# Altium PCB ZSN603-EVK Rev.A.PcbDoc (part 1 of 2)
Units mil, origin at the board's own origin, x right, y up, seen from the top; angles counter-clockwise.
Board outline 3937.01 x 3149.67 mil, 2 copper layers (Top Layer, Bottom Layer); 139 components, 76 nets, 380 pads, 360 vias.
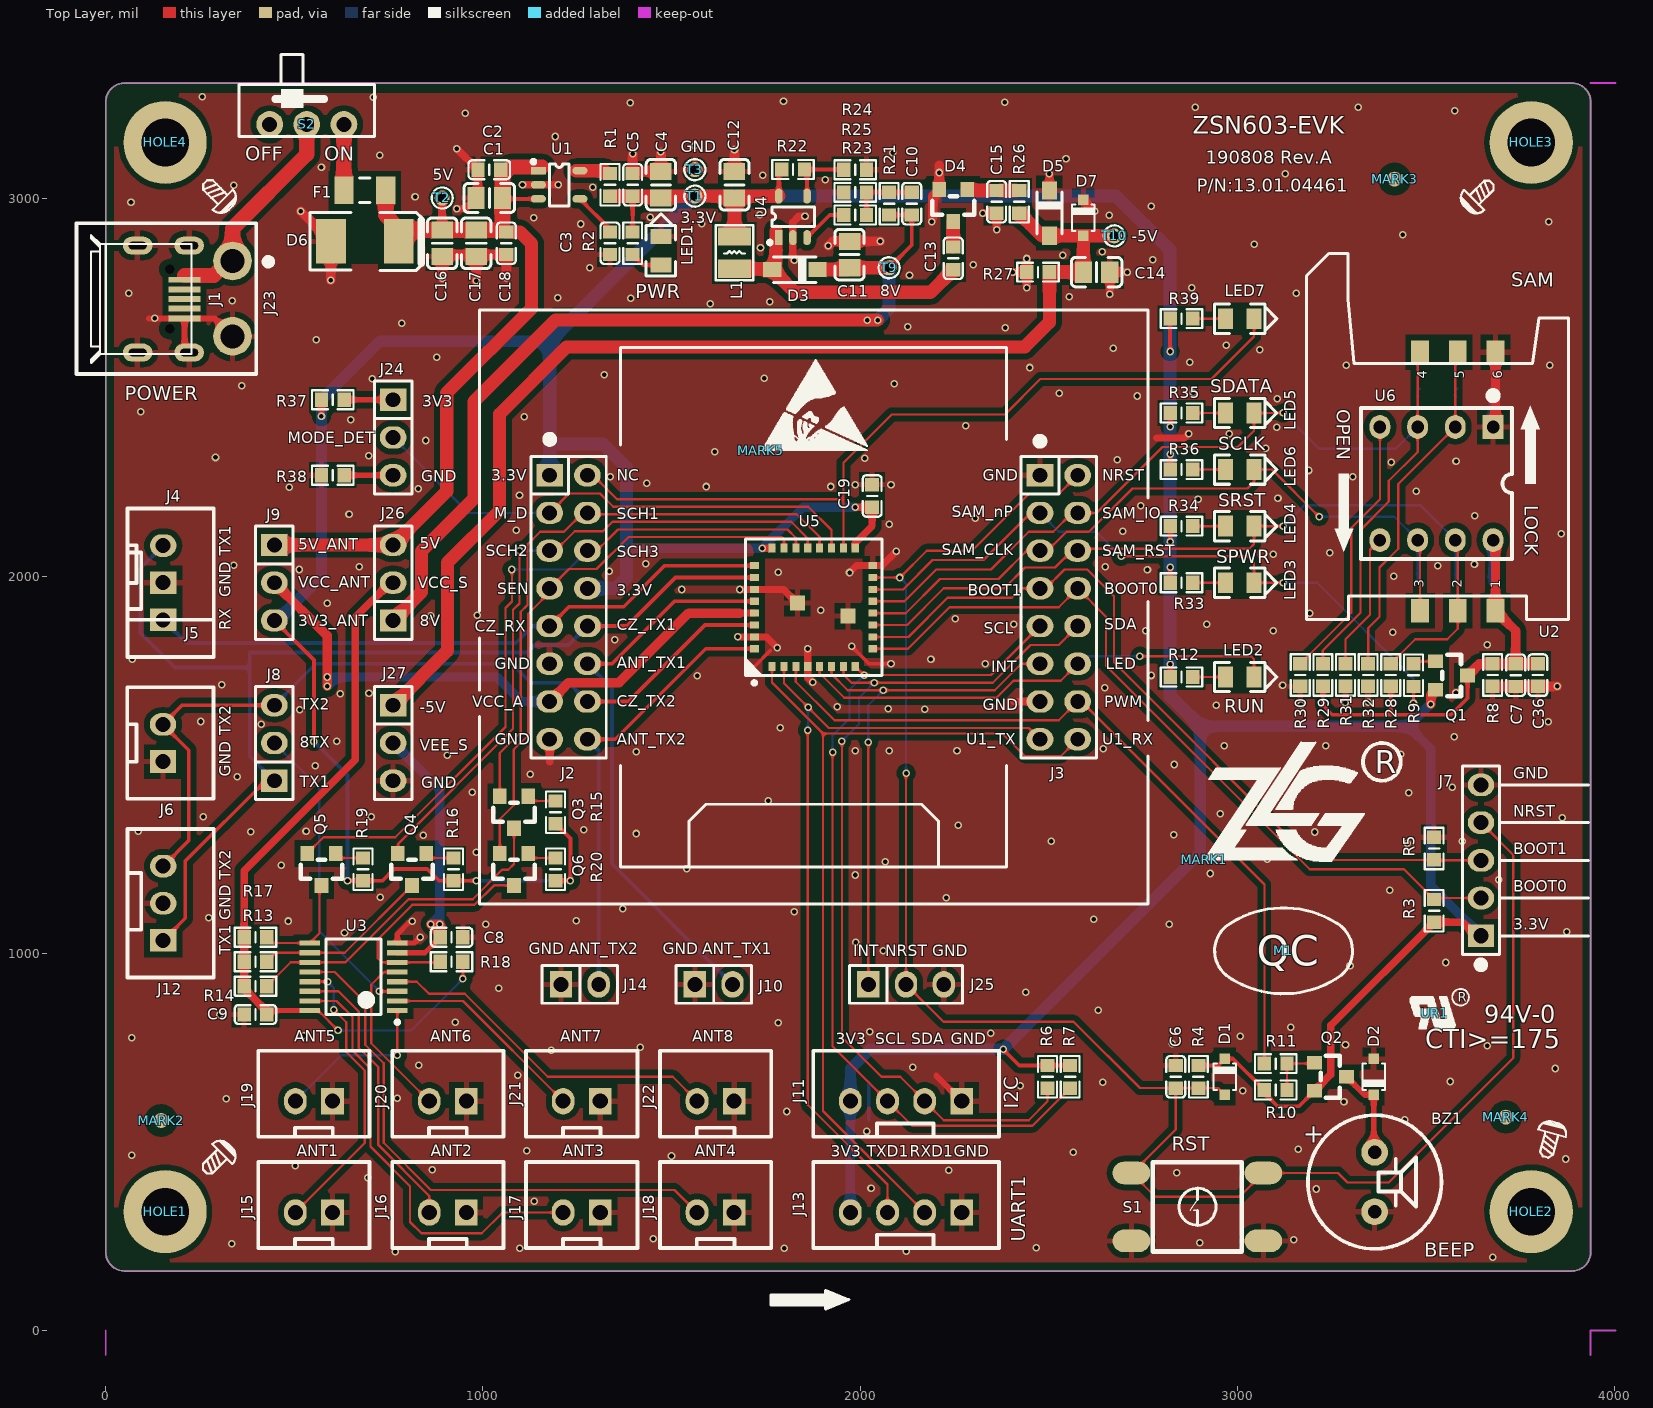
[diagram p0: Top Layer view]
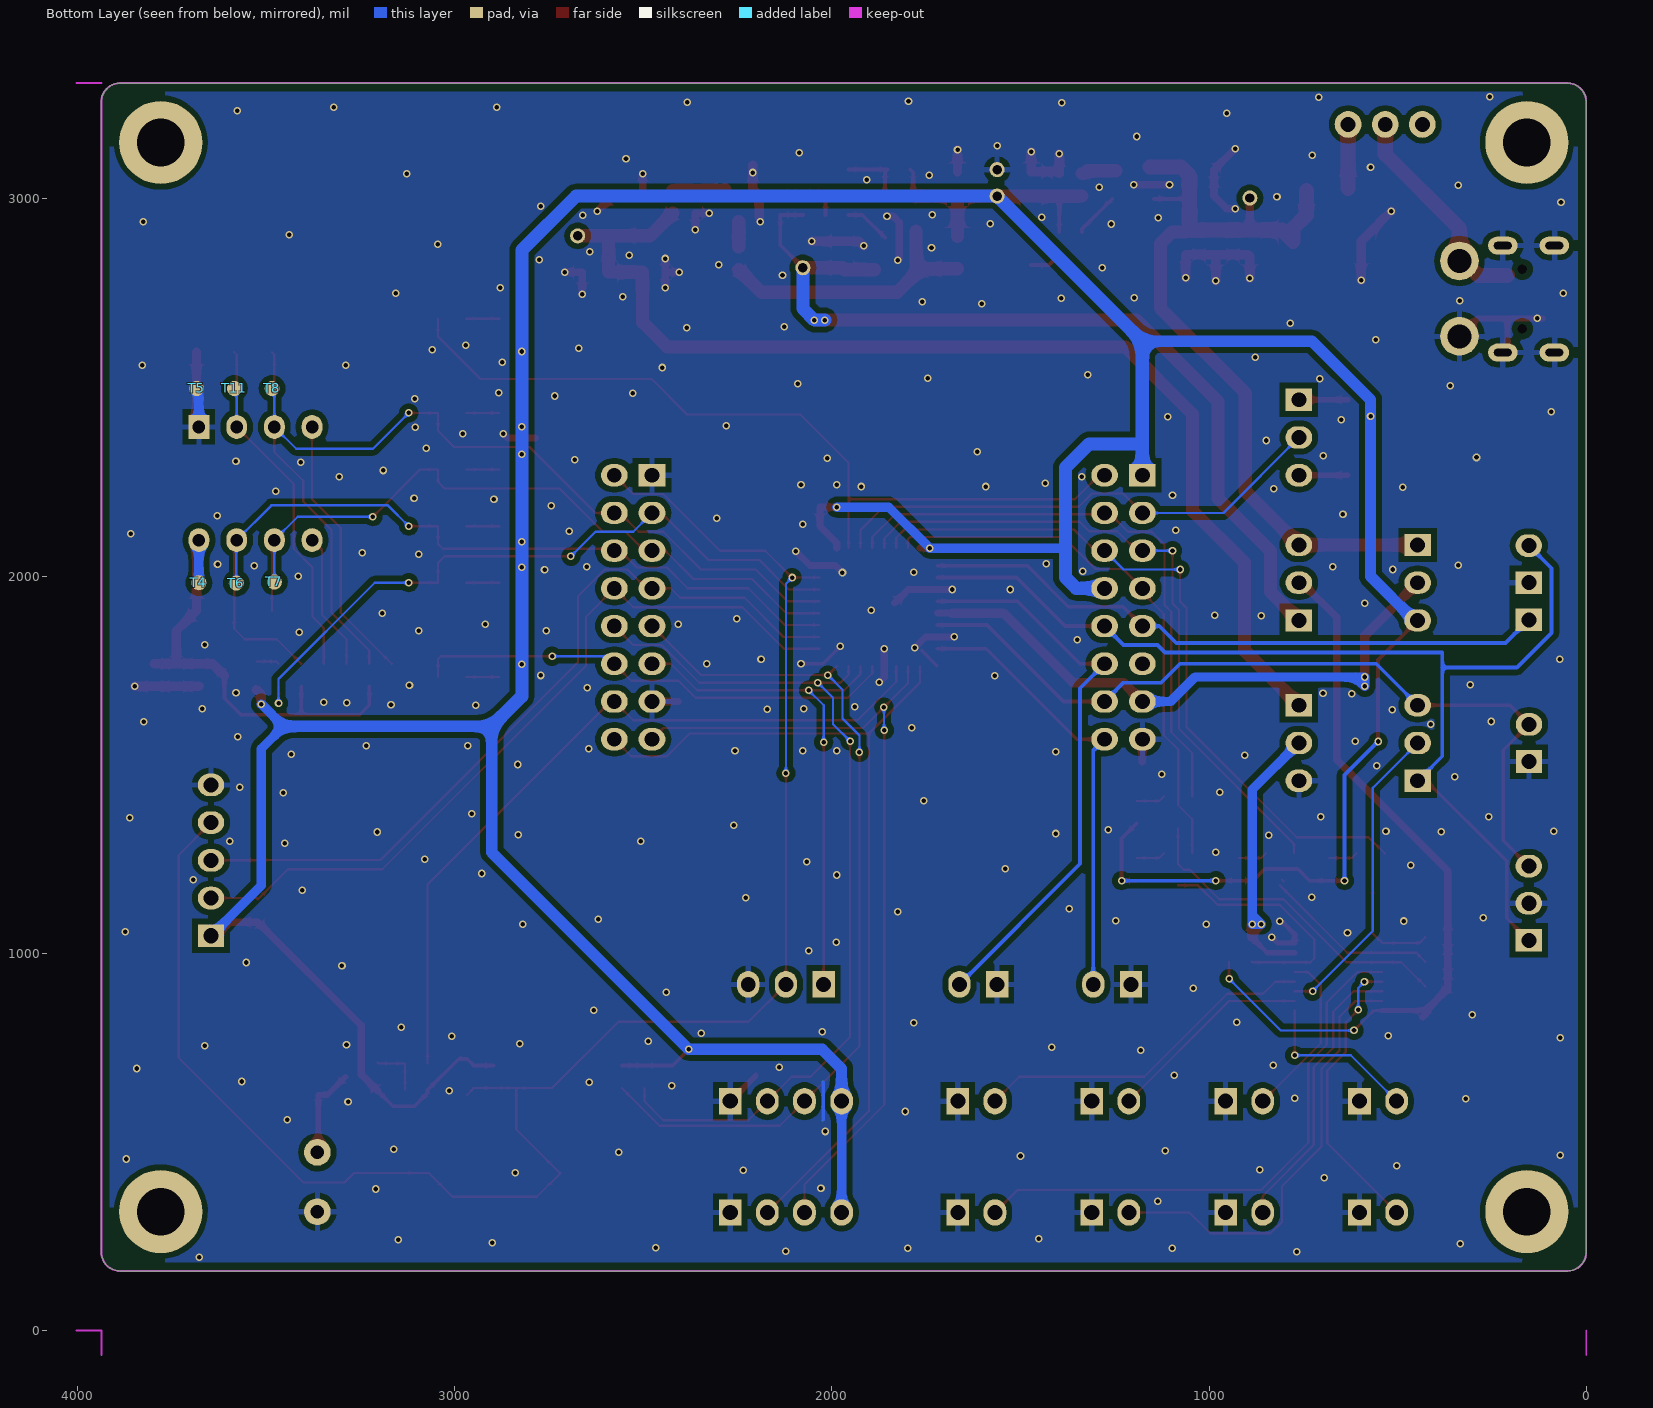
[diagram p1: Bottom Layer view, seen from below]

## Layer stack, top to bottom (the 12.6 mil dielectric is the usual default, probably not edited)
Top Solder: solder mask 0.4, Solder Resist, Dk 3.5
Top Layer: signal copper 1.4
Dielectric1: dielectric 12.6, FR-4, Dk 4.8
Bottom Layer: signal copper 1.4
Bottom Solder: solder mask 0.4, Solder Resist, Dk 3.5

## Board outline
0,207.54 ccw(c50,207.54) 49.56,157.54 3886.97,157.54 3886.97,157.48 ccw(c3886.97,207.48) 3936.97,207.04 3936.97,3257.54 ccw(c3887.46,3257.54) 3887.89,3307.04 3887.89,3307.15 49.57,3307.15 49.96,3307.11 ccw(c49.96,3257.11) -0.04,3257.54

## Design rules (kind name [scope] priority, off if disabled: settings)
Clearance Clearance_Keepout [OnLayer('Keep-Out Layer')] p1: gap=20
Clearance Clearance_Manual [OnLayer('Bottom Layer') and IsSMTPin vs IsPadHoleValid>   (  HasFootprint('PAD-35/50') or   HasFootprint('HOLE-3.2') or  HasFootprint('HOLE-3.2 - Screw') or   HasFootprint('HOLE4.22-SMT') or   HasFootprint('Mou Hole-300D450W310H-SMD') or    HasFootprint('AW6748') or  HasFootprint('IDCS80P500W-20X2-F')  )] p2: gap=50
Clearance Clearance_Via2Via [IsVia vs IsVia] p3: gap=6
Clearance Clearance_Poly2All [InPoly] p4: gap=15
Clearance Clearance_TP [HasFootprint('PAD-40') vs HasFootprint('PAD-40')] p5: gap=50
Clearance [All] p6: gap=6
ComponentClearance [All] p1 off: gap=10 collisioncheckmode=3 verticalgap=10 showdistances=FALSE
DiffPairsRouting [All] p1: maxlimit=8 minlimit=8 mostfreqgap=8 toplayer_minwidth=15 toplayer_maxwidth=15 toplayer_prefwidth=15 bottomlayer_minwidth=15 bottomlayer_maxwidth=15 bottomlayer_prefwidth=15 maxuncoupledlength=500
HoleSize [All] p1: absolutevalues=TRUE maxlimit=1000 minlimit=1 maxpercent=80.000 minpercent=20.000
HoleToHoleClearance [All] p1 off: gap=10 allowstackedmicrovias=TRUE
MinimumSolderMaskSliver [All] p1 off: minsoldermaskwidth=4
PlaneClearance PlaneClearance_Full [IsVia] p1: clearance=9
PlaneClearance [All] p2: clearance=20
PlaneConnect PlaneConnect_Full [IsVia] p1: planeconnectstyle=Direct reliefexpansion=20 reliefentries=4 reliefconductorwidth=10 reliefairgap=10
PlaneConnect [All] p2: planeconnectstyle=Relief reliefexpansion=10 reliefentries=4 reliefconductorwidth=15 reliefairgap=10
PolygonConnect PolygonConnect_SMDHole [HasFootprint('Mou Hole-300D450W310H-SMD') or HasFootprint('Mou Hole-373D600H-SMD')] p1: connectstyle=Relief reliefconductorwidth=80 reliefentries=4 polygonreliefangle="45 Angle" airgapwidth=20
PolygonConnect PolygonConnect_Full [IsVia or   HasFootprint('PAD-40') or   HasFootprint('PAD-35/50') or  HasFootprint('HOLE-3.2') or   HasFootprint('HOLE-3.2 - Screw')] p2: connectstyle=Direct reliefconductorwidth=10 reliefentries=4 polygonreliefangle="90 Angle" airgapwidth=10
PolygonConnect [All] p3: connectstyle=Relief reliefconductorwidth=15 reliefentries=4 polygonreliefangle="90 Angle" airgapwidth=15
RoutingVias [All] p1: holewidth=12 width=20 viastyle="Through Hole" minholewidth=12 minwidth=20 maxholewidth=12 maxwidth=20
SilkToSilkClearance [IsDesignator] p1: silktosilkclearance=2
SilkToSolderMaskClearance [IsPad vs IsDesignator] p1: minsilkscreentomaskgap=2 clearancetoexposedcopper=TRUE
SolderMaskExpansion [All] p1: expansion=4
Width [All] p1: maxlimit=100 minlimit=6 preferedwidth=6
21 further rules are at their usual default settings.

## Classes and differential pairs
component class U_07: C10 C11 C12 C13 C14 C15 D3 D4 D5 D7 L1 R21 R22 R23 R24 R25 R26 R27 T9 T10 U4
component class U_06: C8 C9 J26 J27 Q3 Q4 Q5 Q6 R13 R14 R15 R16 R17 R18 R19 R20 U3
component class U_05: BZ1 D2 J15 J16 J17 J18 J19 J20 J21 J22 LED2 Q2 R10 R11 R12
component class U_04: C7 C36 LED3 LED4 LED5 LED6 Q1 R8 R9 R28 R29 R30 R31 R32 R33 R34 R35 R36 T4 T5 T6 T7 T8 T11 U2 U6
component class "01. Main": HOLE1 HOLE2 HOLE3 HOLE4 M1 MARK1 MARK2 MARK3 MARK4 MARK5 UR1
component class U_02: C1 C2 C3 C4 C5 C16 C17 C18 D6 F1 J1 J23 LED1 R1 R2 S2 T1 T2 T3 U1
component class U_03: C6 C19 D1 J2 J3 J4 J5 J6 J7 J8 J9 J10 J11 J12 J13 J14 J24 J25 LED7 R3 R4 R5 R6 R7 R37 R38 R39 S1 U5

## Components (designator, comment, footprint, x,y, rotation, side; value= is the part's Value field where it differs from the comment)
BZ1 "BUZZER2" BUZZ-4/9 3364.24,393.4 r270 top
C1 "106" 0805C 1016.97,3002.48 r180 top
C2 "105" 0603C 1016.97,3077.48 r180 top
C3 "103" 0603C 1336.97,2882.48 r270 top
C4 "475" 0805C 1471.97,3037.48 r90 top
C5 "104,±10%" 0603C 1396.97,3037.48 r90 top
C6 "0.1μF" 0603C 2836.97,672.48 r90 top
C7 "104" 0603C 3738.24,1737.4 r270 top
C8 "104" 0603C 916.97,1042.48 r0 top
C9 "104" 0603C 396.97,837.48 r180 top
C10 "200P" 0603C 2136.97,2987.48 r90 top
C11 "475,4.7μF" 0805C 1971.97,2852.48 r90 top
C12 "10μF,±10%" 0805C 1666.97,3037.48 r90 top
C13 "0.1μF" 0603C 2246.97,2842.48 r90 top
C14 "10μF,±10%" 0805C 2627,2806 r0 top
C15 "0.1μF" 0603C 2361.97,2992.48 r90 top
C16 "226" 0805C 891.97,2882.48 r270 top
C17 "226" 0805C 981.97,2882.48 r270 top
C18 "103" 0603C 1061.97,2882.48 r270 top
C19 "GRM188R61A475KE15D,4.7uF" 0603C 2031.97,2212.48 r90 top
C36 "104" 0603C 3796.97,1737.48 r270 top
D1 "1N4148" SOD-323 2966.97,672.48 r90 top
D2 "DIODE1" SOD-323 3361.97,672.48 r270 top
D3 "MBR0520LT1G" SOD-123 1826.97,2812.48 r0 top
D4 "BAV99" SOT-23 2246.97,2982.48 r270 top
D5 "3V,200mW" SOD-123 2501.97,2962.48 r90 top
D6 "SMBJ5.0A" SOD-1812D 686.97,2887.48 r0 top
D7 "BZX384-C5V1" SOD-323 2591.97,2949.98 r90 top
F1 "SMD1206P200TF" FUSE320X165X160 686.97,3022.48 r0 top
HOLE1 "HOLE - 螺丝孔" "HOLE-3.2 - Screw" 157.44,314.96 r0 top
HOLE2 "HOLE - 螺丝孔" "HOLE-3.2 - Screw" 3779.49,314.96 r30 top
HOLE3 "HOLE - 螺丝孔" "HOLE-3.2 - Screw" 3779.49,3149.61 r180 top
HOLE4 "HOLE - 螺丝孔" "HOLE-3.2 - Screw" 157.44,3149.61 r270 top
J1 "A01SB141B1-261,MicroUSB插座" MICROUSB-5S -0.04,2734.54 r270 top
J2 "HEADER 8X2" IDC-16-2.54 1226.97,1917.48 r270 top
J3 "HEADER 8X2" IDC-16-2.54 2526.97,1917.48 r270 top
J4 "2.5-3T,180°" CON250P580W100D50S-3DIP 171.97,1982.48 r90 top
J5 "2.5-2T,180°" CON250P580W100D50S-2DIP 171.97,2031.69 r90 top
J6 "2.5-2T,180°" CON250P580W100D50S-2DIP 171.38,1557.48 r90 top
J7 "" SIP-5-2.54-6.0-R90 3646.24,1246.4 r90 top
J8 "ANT_SEL" SIP-3-2.54 446.97,1557.48 r90 top
J9 "PWR_ANT" SIP-3-2.54 446.97,1982.48 r270 top
J10 "CON2" SIP-2-2.54 1611.97,917.48 r0 top
J11 "2.54-4T,180°" CON250P580W100D50S-4DIP 2121.97,627.48 r180 top
J12 "2.5-3T,180°" CON250P580W100D50S-3DIP 171.97,1132.48 r90 top
J13 "2.54-4T,180°" CON250P580W100D50S-4DIP 2121.97,332.48 r180 top
J14 "CON2" SIP-2-2.54 1256.97,917.48 r0 top
J15 "ANT1" CON250P580W100D50S-2DIP 551.97,332.48 r180 top
J16 "ANT2" CON250P580W100D50S-2DIP 906.97,332.48 r180 top
J17 "ANT3" CON250P580W100D50S-2DIP 1261.97,332.48 r180 top
J18 "ANT4" CON250P580W100D50S-2DIP 1616.97,332.48 r180 top
J19 "ANT5" CON250P580W100D50S-2DIP 551.97,627.48 r180 top
J20 "ANT6" CON250P580W100D50S-2DIP 906.97,627.48 r180 top
J21 "ANT7" CON250P580W100D50S-2DIP 1261.97,627.48 r180 top
J22 "ANT8" CON250P580W100D50S-2DIP 1616.97,627.48 r180 top
J23 "2EDGR/2EDGK-5.08-02P-14-00AH" CON508P1210W160D445S-2RA 160.96,2735.54 r270 top
J24 "CON3" SIP-3-2.54 761.97,2367.48 r270 top
J25 "CON3" SIP-3-2.54 2121.97,917.48 r0 top
J26 "CON3" SIP-3-2.54 761.97,1982.48 r90 top
J27 "CON3" SIP-3-2.54 761.97,1557.48 r270 top
L1 "MPH252012C2R2MT,2.2μH" INDC2520X10N 1666.97,2857.48 r270 top
LED1 "0805QRC,红色" LED-0805 1471.97,2862.48 r90 top
LED2 "0805QGC,绿色" LED-0805 3006.97,1732.48 r0 top
LED3 "0805QGC,绿色" LED-0805 3006.97,1982.48 r0 top
LED4 "0805QGC,绿色" LED-0805 3006.97,2132.48 r0 top
LED5 "0805QGC,绿色" LED-0805 3006.97,2432.48 r0 top
LED6 "0805QGC,绿色" LED-0805 3006.97,2282.48 r0 top
LED7 "0805QGC,绿色" LED-0805 3006.97,2682.48 r0 top
M1 "ZY QC" ZY_QC 3122.97,1006.48 r0 top
MARK1 "ZLG" ZLG1.0 2911.97,1247.48 r0 top
MARK2 "MARKER" MARKER-C-1.0M 146.96,556.54 r0 top
MARK3 "MARKER" MARKER-C-1.0M 3416.97,3052.48 r0 top
MARK4 "MARKER" MARKER-C-1.0M 3711.97,565.48 r0 top
MARK5 "ZY_ESD-MARK" ZY_ESD-7 1736.97,2332.48 r0 top
Q1 "PNP-1" SOT-23 3568.24,1736.4 r0 top
Q2 "PNP-1" SOT-23 3246.97,672.48 r0 top
Q3 "SS8050LT(1.5A),SOT-23" SOT-23 1082.33,1373.83 r270 top
Q4 "SS8050LT(1.5A),SOT-23" SOT-23 811.97,1222.48 r270 top
Q5 "SS8050LT(1.5A),SOT-23" SOT-23 571.97,1222.48 r270 top
Q6 "SS8050LT(1.5A),SOT-23" SOT-23 1082.33,1222.48 r270 top
R1 "0Ω" 0603R 1336.97,3037.48 r270 top
R2 "1.5kΩ" 0603R 1396.97,2882.48 r270 top
R3 "10kΩ" 0603R 3521.97,1112.48 r270 top
R4 "100KΩ" 0603R 2896.97,672.48 r90 top
R5 "10kΩ" 0603R 3521.97,1277.48 r270 top
R6 "10KΩ,±1%" 0603R 2496.97,672.48 r90 top
R7 "10KΩ,±1%" 0603R 2556.97,672.48 r90 top
R8 "10KΩ,±1%" 0603R 3676.97,1737.48 r270 top
R9 "2KΩ" 0603R 3467.24,1737.4 r90 top
R10 "10KΩ,±1%" 0603R 3101.97,637.48 r180 top
R11 "1.5KΩ" 0603R 3101.97,707.48 r0 top
R12 "1.5KΩ" 0603R 2851.97,1732.48 r0 top
R13 "100KΩ" 0603R 396.97,977.48 r180 top
R14 "100KΩ" 0603R 396.97,912.48 r180 top
R15 "100KΩ" 0603R 1192.33,1373.83 r270 top
R16 "100KΩ" 0603R 921.97,1222.48 r270 top
R17 "100KΩ" 0603R 396.97,1042.48 r180 top
R18 "100KΩ" 0603R 916.97,977.48 r0 top
R19 "100KΩ" 0603R 681.97,1222.48 r270 top
R20 "100KΩ" 0603R 1192.33,1222.48 r270 top
R21 "120KΩ,±1%" 0603R 2076.97,2987.48 r270 top
R22 "30KΩ" 0603R 1822.44,3077.98 r180 top
R23 "100KΩ" 0603R 1986.97,2957.48 r180 top
R24 "22K,±1%" 0603R 1986.97,3077.48 r180 top
R25 "22K,±1%" 0603R 1986.97,3017.48 r0 top
R26 "470Ω" 0603R 2421.97,2992.48 r270 top
R27 "100KΩ" 0603R 2472,2806 r0 top
R28 "10KΩ,±1%" 0603R 3406.97,1737.48 r270 top
R29 "10KΩ,±1%" 0603R 3226.97,1737.48 r270 top
R30 "2KΩ" 0603R 3166.97,1737.48 r90 top
R31 "2KΩ" 0603R 3286.97,1737.48 r90 top
R32 "2KΩ" 0603R 3346.97,1737.48 r90 top
R33 "2KΩ" 0603R 2851.97,1982.48 r180 top
R34 "2KΩ" 0603R 2851.97,2132.48 r180 top
R35 "2KΩ" 0603R 2851.97,2432.48 r180 top
R36 "2KΩ" 0603R 2851.97,2282.48 r180 top
R37 "10kΩ" 0603R 601.97,2467.48 r0 top
R38 "10kΩ" 0603R 601.97,2267.48 r0 top
R39 "2KΩ" 0603R 2851.97,2682.48 r180 top
S1 "TS0641-0501B,6×6×5.0mm" KEY-6S 2894.24,327.4 r0 top
S2 "9*3.6*5mm,MSS12D19G2" MSS12D19G2 532.96,3197.54 r0 top
T1 "3.3V" PAD-25/40 1561.97,3007.48 r0 top
T2 "5V" PAD-25/40 891.97,3002.48 r0 top
T3 "GND" PAD-25/40 1561.97,3077.48 r0 top
T4 "TEST-DOT" PAD-40 3678.24,1982.4 r270 bottom
T5 "TEST-DOT" PAD-40 3684.24,2497.4 r270 bottom
T6 "TEST-DOT" PAD-40 3579.24,1981.4 r270 bottom
T7 "TEST-DOT" PAD-40 3478.24,1984.4 r270 bottom
T8 "TEST-DOT" PAD-40 3484.24,2497.4 r0 bottom
T9 "8V" PAD-25/40 2076.97,2817.48 r90 top
T10 "-5V" PAD-25/40 2674,2902 r0 top
T11 "TEST-DOT" PAD-40 3584.24,2497.4 r180 bottom
U1 "CAT6219-330TD" SOT-23-5 1201.97,3037.48 r0 top
U2 "掀盖式1.8高SIM卡座" SIM-CARD-24.65X17.65-6P 3531.24,2284.4 r180 top locked
U3 "HEF4051BTT" SOP65P640X110-16N 656.97,937.48 r180 top
U4 "MP1541DJ" SOT-23-5 1821.97,2952.48 r90 top
U5 "ZSN600,LGA32" ZSN600 1876.97,1917.48 r90 top
U6 "HEADER 4X2R" DIP762W62P254L1016H500Q8P 3528.24,2245.4 r270 top
UR1 "UR" ZY_UR-3X2 3523.97,840.48 r0 top

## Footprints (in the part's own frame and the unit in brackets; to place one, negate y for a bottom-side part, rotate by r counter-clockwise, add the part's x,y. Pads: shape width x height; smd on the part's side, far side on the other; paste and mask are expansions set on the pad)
0603C [mm]
  rect 0.9x0.95 smd: 1(-0.762,0) 2(0.762,0)
  silkscreen extent -1.4,-0.64 1.4,0.64, body extent -0.79,-0.38 0.81,0.42, height 0.3
0603R [mm]
  rect 0.9x0.95 smd: 1(-0.762,0) 2(0.762,0)
  silkscreen extent -1.4,-0.64 1.4,0.64, body extent -0.8,-0.4 0.8,0.4, height 0.3
0805C [mm]
  rect 1.15x1.45 smd: 1(-0.889,0) 2(0.889,0)
  silkscreen extent -1.7,-0.99 1.7,0.99, body extent -1,-0.63 1,0.63, height 0.78
BUZZ-4/9 [mm]
  round 1.8 hole 0.9: 1(-2,0) 2(2,0)
  silkscreen extent -4.5,-4.5 4.5,4.5
CON250P580W100D50S-2DIP [mil]
  rect 60x70 hole 40: 1(-49.21,19.69)
  oval 60x70 hole 40: 2(49.21,19.69)
  silkscreen extent -148,-114 148,114, body extent -147,-120 148,116, height 276
CON250P580W100D50S-3DIP [mil]
  rect 60x70 hole 40: 1(-98.43,19.69)
  oval 60x70 hole 40: 2(0,19.69) 3(98.43,19.69)
  silkscreen extent -197,-114 197,114, body extent -197,-119 197,117, height 276
CON250P580W100D50S-4DIP [mil]
  rect 60x70 hole 40: 1(-147.64,19.69)
  oval 60x70 hole 40: 2(-49.21,19.69) 3(49.21,19.69) 4(147.64,19.69)
  silkscreen extent -246,-114 246,114, body extent -244,-119 249,117, height 276
CON508P1210W160D445S-2RA [mm]
  round 2.6 hole 1.6: 1(-2.54,4.45) 2(2.54,4.45)
  silkscreen extent -5.08,-6.05 5.08,7.06
DIP762W62P254L1016H500Q8P [mm]
  rect 1.6x1.4 hole 0.85: 1(-3.81,3.81)
  oval 1.6x1.4 hole 0.85: 2(-3.81,1.27) 3(-3.81,-1.27) 4(-3.81,-3.81) 5(3.81,-3.81) 6(3.81,-1.27) 7(3.81,1.27) 8(3.81,3.81)
  silkscreen extent -6.17,-5.08 5.08,5.08
FUSE320X165X160 [mm] "Chip Capacitor, 2-Leads, Body 3.20x1.65mm, IPC Medium Density"
  rect 1.3x1.85 smd: 1(-1.4,0) 2(1.4,0)
  silkscreen extent -0.35,-0.82 0.35,0.82, body extent -1.7,-0.9 1.7,0.9, height 1.6
"HOLE-3.2 - Screw" [mm]
  round 5.6 hole 3.2: 1(0,0)
  silkscreen extent 2.55,2.57 4.74,4.77
IDC-16-2.54 [mm]
  rect 1.5x1.8 hole 1: 1(-8.89,-1.27)
  oval 1.5x1.8 hole 1: 2(-8.89,1.27) 3(-6.35,-1.27) 4(-6.35,1.27) 5(-3.81,-1.27) 6(-3.81,1.27) 7(-1.27,-1.27) 8(-1.27,1.27) 9(1.27,-1.27) 10(1.27,1.27) 11(3.81,-1.27) 12(3.81,1.27) 13(6.35,-1.27) 14(6.35,1.27) 15(8.89,-1.27) 16(8.89,1.27)
  silkscreen extent -11.55,-2.54 10.16,2.54, body extent -10.16,-2.54 10.16,2.54, height 7.58
INDC2520X10N [mm] "Chip Inductor, 2-Leads, Body 2.50x2.00mm, IPC Medium Density"
  rect 1.23x2.22 smd: 1(-1.085,0) 2(1.085,0)
  Top Layer pour cut-out: -0.475,-1.225 -0.475,1.225 0.475,1.225 0.475,-1.225
  silkscreen extent -1.85,-1.27 1.85,1.27, body extent -1.35,-1.1 1.35,1.1, height 1
KEY-6S [mil]
  oval 100x60 smd: 1(-175,90) 2(-175,-90) 3(175,-90) 4(175,90)
  silkscreen extent -118,-118 118,118, body extent -201,-122 201,122, height 268
LED-0805 [mm] "170907内距改0.9mm"
  rect 1.014x1.4 smd: 1(-0.957,0) 2(0.957,0)
  silkscreen extent -1.7,-0.99 2.49,0.99, body extent -1,-0.64 1,0.64, height 1.1
MARKER-C-1.0M [mm]
  round 1 smd paste-1.016 mask+0.5: 0(0,0)
  Top Layer pour cut-out: -1.1,0 -1.016,-0.421 -0.778,-0.778 -0.421,-1.016 0,-1.1 0,-1.1 0.421,-1.016 0.778,-0.778 1.016,-0.421 1.1,0 1.1,0 1.016,0.421 0.778,0.778 0.421,1.016 0,1.1 0,1.1 -0.421,1.016 -0.778,0.778 -1.016,0.421 -1.1,0
MICROUSB-5S [mm]
  oval 1.2x2 on Top Paste: 0(-3.6,2.15) 0(-3.6,5.62) 0(3.6,2.15) 0(3.6,5.62)
  round 0.54 hole 0.65 unplated: 0(-2,4.3) 0(2,4.3)
  rect 0.4x2.15 smd: 1(-1.3,5.31) 2(-0.65,5.31) 3(0,5.31) 4(0.65,5.31) 5(1.3,5.31)
  oval 1.2x2 hole 0.5 slot 1.2 at 90 deg: 6(-3.6,5.62) 7(3.6,5.62) 8(-3.6,2.15) 9(3.6,2.15)
  silkscreen extent -4.3,-0.99 4.3,5.77
MSS12D19G2 [mm]
  round 1.8 hole 1: 1(-2.5,0) 2(0,0) 3(2.5,0)
  silkscreen extent -4.55,-0.8 4.55,4.7
PAD-25/40 [mil]
  round 40 hole 25: 1(0,0)
  silkscreen extent -28,-28 28,28
PAD-40 [mil]
  round 40 smd paste-43.31: 1(0,0)
SIM-CARD-24.65X17.65-6P [mm]
  rect 1.2x1.6 smd mask+0.051: 1(-3.9,9.55) 2(-1.36,9.55) 3(1.18,9.55) 4(1.18,-7.85) 5(-1.36,-7.85) 6(-3.9,-7.85)
  silkscreen extent -8.82,-14.5 8.82,10.15
SIP-2-2.54 [mm]
  rect 1.5x1.8 hole 1: 1(-1.27,0)
  oval 1.5x1.8 hole 1: 2(1.27,0)
  silkscreen extent -2.54,-1.27 2.54,1.27, body extent -2.54,-1.27 2.54,1.27, height 7.58
SIP-3-2.54 [mm]
  rect 1.5x1.8 hole 1: 1(-2.54,0)
  oval 1.5x1.8 hole 1: 2(0,0) 3(2.54,0)
  silkscreen extent -3.81,-1.27 3.81,1.27, body extent -3.81,-1.27 3.81,1.27, height 7.58
SIP-5-2.54-6.0-R90 [mil] "引脚伸出部分为6.0mm"
  rect 60x70 hole 40: 1(-200,0)
  oval 60x70 hole 40: 2(-100,0) 3(0,0) 4(100,0) 5(200,0)
  silkscreen extent -286,-285 250,49
SOD-123 [mm]
  rect 1.22x1 smd: 1(-1.524,0) 2(1.524,0)
  silkscreen extent -1.42,-0.85 1.43,0.85, body extent -1.85,-0.81 1.85,0.79, height 1.2
SOD-323 [mil]
  rect 28x28 smd: 1(-47.5,0) 2(47.5,0)
  silkscreen extent -35,-30 35,30, body extent -51,-26 51,25, height 39
SOD-1812D [mm]
  rect 2x3 smd: 1(-2.286,0) 2(2.286,0)
  Top Layer pour cut-out: -1.27,1.499 -1.27,-1.499 1.245,-1.499 1.245,1.499
  silkscreen extent -3.71,-1.95 3.86,1.95, body extent -2.77,-1.96 2.83,1.94, height 2.5
SOP65P640X110-16N [mm] "TSOP, 16-Leads, Body 5.00x4.40mm, Pitch 0.65mm, IPC Medium Density"
  rect 1.4x0.35 smd: 1(-2.95,2.275) 2(-2.95,1.625) 3(-2.95,0.975) 4(-2.95,0.325) 5(-2.95,-0.325) 6(-2.95,-0.975) 7(-2.95,-1.625) 8(-2.95,-2.275) 9(2.95,-2.275) 10(2.95,-1.625) 11(2.95,-0.975) 12(2.95,-0.325) 13(2.95,0.325) 14(2.95,0.975) 15(2.95,1.625) 16(2.95,2.275)
  silkscreen extent -3.08,-2.55 1.85,3.17, body extent -2.25,-2.55 2.25,2.55, height 1.1
SOT-23 [mil]
  rect 40x36 smd: 1(-42.5,37.4) 2(-42.5,-37.4) 3(42.5,0)
  silkscreen extent -25,-56 25,56, body extent -47,-57 50,58, height 39
SOT-23-5 [mil]
  rect 40x20 smd: 1(-55,37.4)
  oval 40x20 smd: 2(-55,0) 3(-55,-37.4) 4(55,-37.4) 5(55,37.4)
  silkscreen extent -73,-57 26,66, body extent -55,-57 55,57, height 43
ZLG1.0 [mil]
  silkscreen extent 0,-4 522,312
ZSN600 [mm]
  rect 0.6x0.48 smd mask+0.07: 1(-3.98,2.8) 2(-3.98,2) 3(-3.98,1.2) 4(-3.98,0.4) 5(-3.98,-0.4) 6(-3.98,-1.2) 7(-3.98,-2) 8(-3.98,-2.8) 17(3.98,-2.8) 18(3.98,-2) 19(3.98,-1.2) 20(3.98,-0.4) 21(3.98,0.4) 22(3.98,1.2) 23(3.98,2) 24(3.98,2.8)
  rect 0.48x0.6 smd mask+0.07: 9(-2.8,-3.98) 10(-2,-3.98) 11(-1.2,-3.98) 12(-0.4,-3.98) 13(0.4,-3.98) 14(1.2,-3.98) 15(2,-3.98) 16(2.8,-3.98) 25(2.8,3.98) 26(2,3.98) 27(1.2,3.98) 28(0.4,3.98) 29(-0.4,3.98) 30(-1.2,3.98) 31(-2,3.98) 32(-2.8,3.98)
  rect 1x1 smd mask+0.07: 33(0.28,1.1) 34(-0.6,-2.3)
  silkscreen extent -5.22,-4.6 4.6,4.6, body extent -4.55,-4.55 4.55,4.55, height 0.8
ZY_ESD-7 [mil]
  silkscreen extent 1,1 284,242
ZY_QC [mil]
  silkscreen extent -183,-114 183,114
ZY_UR-3X2 [mil]
  silkscreen extent -67,-40 90,65

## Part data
BZ1: library part 1.06.09.0016, "Buzzer有极性"
C1: library part 1.02.02.0055, "106,10μF,±10%,10V,X5R,0805,RoHS"
C2: library part 1.02.01.0036, "105,1μF,±10%,16V,X7R,0603,*,RoHS"
C3: library part 1.02.01.0024, "103,±10%,50V,X7R,0603,*,RoHS"
C4: library part 1.02.02.0064, "475,±10%,16V,X7R,0805,RoHS"
C5: library part 1.02.01.0032, "Capacitor"
C6 C7 C8 C9 C13 C15 C36: library part 1.02.01.0032, "GRM188R71H104KA93D,104,±10%,50V,X7R,0603,muRata,RoHS"
C10: library part 1.02.01.0015, "GRM1885C1H201JA01D,200P,±5%,50V,COG,0603,muRata,RoHS"
C11: library part 1.02.02.0086, "GRM21BR71C475KA73L,475,4.7μF,±10%,16V,X7R,0805,murata,RoHS"
C12 C14: library part 1.02.02.0117, "10μF,±10%,10V,X7R,GRM21BR71A106KE51L,0805,muRata,RoHS"
C16 C17: library part 1.02.02.0059, "GRM21BR60J226ME39L,226,22μF,±20%,6.3V,X5R,0805,muRata,RoHS"
C18: library part 1.02.01.0024, "GRM188R71H103KA01D,103,±10%,50V,X7R,0603,muRata,RoHS"
C19: library part 1.02.01.0080, "GRM188R61A475KE15D,4.7uF,±10%,10V,X5R,0603,muRata,RoHS"
D1: library part 1.04.07.0027, "1N4148,SOD-323,长电,RoHS"
D2: library part 1.04.07.0027, "1N4148,SOD-323,RoHS"
D3: library part 1.04.07.0014, "MBR0520LT1G,SOD-123,ON,RoHS"
D4: library part 1.04.07.0010, "BAV99,SOT-23,NXP,RoHS"
D5: library part 1.04.01.0018, "3V,200mW,MMSZ4683,SOD-123,长电,RoHS"
D6: library part 1.04.03.0001, "SMBJ5.0A,DO-214AA,君耀,RoHS"
D7: library part 04.03.00033, "BZX384-C5V1,SOD-323,NEXPERIA,"
F1: library part 1.06.03.0017, "SMD1206P200TF,1206,Polytronics,RoHS"
J1: library part 1.10.12.0014, "A01SB141B1-261,MicroUSB插座,SMT,艾立信,RoHS"
J4 J12: library part 1.10.06.0010, "2.5-3T,180°,PA46本色,WF2501-WSH03T02,WCON,RoHS"
J5 J6 J15 J16 J17 J18 J19 J20 J21 J22: library part 1.10.06.0009, "2.5-2T,180°,PA46本色,WF2501-WSH02T02,WCON,RoHS"
J7: library part CON5, "Connector"
J8 J9: library part CON3, "Connector"
J10 J14 J24 J25 J26 J27: "Connector"
J11 J13: library part 1.10.06.0011, "2.54-4T,180°,,*"
J23: library part 1.10.06.0027, "2EDGR/2EDGK-5.08-02P-14-00AH,DEGSON,RoHS"
L1: library part 1.03.01.0347, "MPH252012C2R2MT,2.2μH,±20%,700mA,1008,Sunlord,RoHs"
LED1: library part 1.04.05.0001, "0805QRC,红色,0805,RoHS"
LED2 LED3 LED4 LED5 LED6 LED7: library part 1.04.05.0002, "0805QGC,绿色,0805,RoHS"
Q1: library part 1.04.09.0002, "SS8550LT(1.5A),SOT-23,江苏长电,RoHS"
Q2: library part 1.04.09.0002, "PNP Transistor"
Q3 Q4 Q5 Q6: library part 1.04.09.0001, "SS8050LT(1.5A),SOT-23,长电,RoHS"
R1: library part 1.01.01.0001
R2 R11 R12: library part 1.01.01.0037, "1.5KΩ,0603,*,RoHS"
R3 R5 R6 R7 R8 R10 R28 R29 R37 R38: library part 1.01.01.0052, "10KΩ,±1%,0603,*,RoHS"
R4 R13 R14 R15 R16 R17 R18 R19 R20 R23 R27: library part 1.01.01.0062, "100KΩ,0603,*,RoHS"
R9 R30 R31 R32 R33 R34 R35 R36 R39: library part 1.01.01.0038, "2KΩ,0603,*,RoHS"
R21: library part 1.01.01.0064, "120KΩ,±1%,0603,*,RoHS"
R22: library part 1.01.01.0058, "30KΩ,0603,*,RoHS"
R24 R25: library part 1.01.01.0152, "22K,±1%,0603,RoHS"
R26: library part 1.01.01.0032, "470Ω,0603,*,RoHS"
S1: library part 1.09.01.0003, "TS0641-0501B,6×6×5.0mm,黑色,SMD,卷带装,RoHS"
S2: library part 1.09.07.0029, "9*3.6*5mm,MSS12D19G2,东昇,RoHS"
T1 T2 T3 T9 T10: library part TEST-DOT
U1: library part 1.05.10.0321, "CAT6219-330TD,TSOT-23-5,ON,RoHS"
U2: library part 1.10.17.0012
U3: library part 1.05.10.0716, "HEF4051BTT,TSSOP16,Nexperia"
U4: library part 1.05.09.0258, "MP1541DJ,TSOT23-5,MPS,RoHS"
U5: library part 08.08.00853, "ZSN600,LGA32,ZLG"
U6: library part 1.10.02.0001, "DIP-8,300mil,,*"

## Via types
v1: diameter 20, hole 12, Top Layer to Bottom Layer, tented both sides, 360 vias

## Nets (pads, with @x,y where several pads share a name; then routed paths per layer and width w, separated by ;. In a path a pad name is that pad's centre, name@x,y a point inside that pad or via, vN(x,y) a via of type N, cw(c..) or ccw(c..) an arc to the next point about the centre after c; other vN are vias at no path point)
3.3V: C4.1 C5.1 C12.1 C19.1 D1.2 J2.1 J2.8 J7.1 J9.3 J11.4 J13.4 L1.1 Q1.2 Q2.2 R1.2 R2.1 R3.2 R4.2 R6.2 R7.2 R10.2 R12.1 R15.2 R16.2 R19.2 R20.2 R22.2 R33.2 R34.2 R35.2 R36.2 R37.1 R39.2 T1.1 U4.5 U5.17 U5.24 | length 13444
  Top Layer w10: J9.3@446.97,1882.48 551.97,1777.48 v1(551.97,1561.48) ; v1(640.97,1192.48) R19.2@681.97,1192.48 733.97,1192.48 764.62,1223.13 852.62,1223.13 883.26,1192.48 R16.2@921.97,1192.48 v1(981.97,1192.48) ; R20.2@1192.33,1192.48 v1(1231.97,1192.48) 1231.97,1304.19 R15.2@1192.33,1343.83 ; R2.1@1396.97,2912.48 C5.1@1396.97,3007.48 ; U4.5@1784.57,3007.48 1784.57,3070.11 R22.2@1792.44,3077.98 ; v1(2378.97,745.48) 2421.97,702.48 R6.2@2496.97,702.48 R7.2@2556.97,702.48 ; R12.1@2821.97,1732.48 v1(2821.97,1766.48) ; R33.2@2821.97,1982.48 v1(2821.97,2023.48) ; v1(2821.97,2091.48) R34.2@2821.97,2132.48 ; R36.2@2821.97,2282.48 v1(2821.97,2323.48) ; v1(2821.97,2396.48) R35.2@2821.97,2432.48 ; v1(2821.97,2595.48) R39.2@2821.97,2682.48 ; R4.2@2896.97,702.48 2949.47,702.48 D1.2@2966.97,719.98 2989.47,719.98 R10.2@3071.97,637.48 3071.97,629.48 3106.97,594.48 3163.87,594.48 Q2.2@3204.47,635.08
  Top Layer w15: v1(571.97,2423.48) R37.1@571.97,2467.48
  Top Layer w19: v1(1740.67,2074.17) U5.24@1766.74,2074.17 ; U5.17@1987.21,2074.17 1987.21,2087.72 2031.97,2132.48 C19.1@2031.97,2182.48 2031.74,2182.72 v1(1987.21,2182.72)
  Top Layer w20: Q2.2@3204.47,635.08 3247.97,678.58 3247.97,808.48 R3.2@3521.97,1082.48 3596.97,1082.48 3633.06,1046.4 J7.1@3646.24,1046.4
  Top Layer w25: v1(3512.51,1660.48) 3512.51,1685.76 Q1.2@3525.74,1698.99
  Top Layer w35: R1.2@1336.97,3007.48 C5.1@1396.97,3007.48 T1.1@1556.97,3007.48 ; T1.1@1561.97,3007.48 1661.97,3007.48 C12.1@1666.97,3002.48 ; L1.1@1666.97,2900.2 C12.1@1666.97,3002.48 ; U4.5@1784.57,3007.48 1671.97,3007.48 C12.1@1666.97,3002.48
  Bottom Layer w10: v1(551.97,1561.48) 640.97,1472.48 v1(640.97,1192.48) ; v1(981.97,1192.48) v1(1231.97,1192.48)
  Bottom Layer w25: 1380.97,2074.17 v1(1740.67,2074.17) 1849.21,2182.72 v1(1987.21,2182.72) ; J13.4@1974.33,312.8 J11.4@1974.33,607.8 ; v1(3512.51,1660.48) 3453.51,1601.48 3512.97,1542.02 3512.97,1179.66 J7.1@3646.24,1046.4
  Bottom Layer w30: J9.3@446.97,1882.48 454.97,1882.48 571.97,1999.48 v1(571.97,2423.48) 571.97,2467.48 726.97,2622.48 1176.97,2622.48 ; J11.4@1974.33,607.8 1974.33,693.84 2025.97,745.48 2379.97,745.48 2901.97,1267.48 2901.97,1601.48 3453.51,1601.48
  Bottom Layer w35: J2.1@1176.97,2267.48 1176.97,2351.48 ; J2.8@1276.97,1967.48 1351.97,1967.48 1380.97,1996.48 1380.97,2287.48 1317.97,2350.48 1177.97,2350.48 1176.97,2351.48 ; 2901.97,1601.48 2821.97,1681.48 v1(2821.97,2023.48) v1(2821.97,2091.48) v1(2821.97,2323.48) v1(2821.97,2396.48) v1(2821.97,2595.48) 2821.97,2864.03 2678.52,3007.48 T1.1@1561.97,3007.48 1176.97,2622.48 1176.97,2351.48
5V: C1.1 C2.1 C16.1 C17.1 C18.1 D6.2 F1.2 J9.1 J26.3 T2.1 U1.1 U1.3 | length 2222.8
  Top Layer w10: C1.1@1051.97,3002.48 1054.37,3000.08 U1.3@1146.97,3000.08
  Top Layer w20: C16.1@891.97,2917.48 T2.1@891.97,3002.48
  Top Layer w35: J9.1@446.97,2082.48 J26.3@761.97,2082.48 903.97,2224.48 903.97,2485.48 1128.97,2710.48 1128.97,2881.48 1097.97,2912.48 C18.1@1061.97,2912.48
  Top Layer w40: F1.2@742.09,3022.48 742.09,2957.36 776.97,2922.48 D6.2@776.97,2887.48 806.97,2917.48 C16.1@891.97,2917.48 C17.1@981.97,2917.48 1051.97,2917.48 C1.1@1051.97,3002.48 1051.97,3062.48 1073.97,3084.48 U1.1@1156.97,3084.48
8V: C10.1 C11.1 D3.2 J26.1 R21.2 T9.1 | length 2424.3
  Top Layer w10: T9.1@2076.97,2817.48 2136.97,2877.48 C10.1@2136.97,2957.48 R21.2@2076.97,2957.48
  Top Layer w35: J26.1@761.97,1882.48 836.97,1957.48 836.97,2066.48 975.97,2205.48 975.97,2462.48 1192.39,2678.9 v1(2018.97,2678.9) v1(2046.39,2678.9) ; D3.2@1886.97,2812.48 1966.97,2812.48 C11.1@1971.97,2817.48 T9.1@2076.97,2817.48
  Bottom Layer w35: v1(2018.97,2678.9) v1(2046.39,2678.9) 2076.97,2709.48 T9.1@2076.97,2817.48
-5V: C14.1 D5.1 D7.1 J27.1 R26.2 R27.2 T10.1 | length 3044.5
  Top Layer w35: J27.1@761.97,1657.48 905.97,1801.48 905.97,2035.48 1043.97,2173.48 1043.97,2429.48 1221.97,2607.48 2436.48,2607.48 2502,2673 R27.2@2502,2806 C14.1@2592,2806 D7.1@2591.97,2902.48 ; R26.2@2421.97,2962.48 2481.97,2902.48 D5.1@2501.97,2902.48 D7.1@2591.97,2902.48 ; T10.1@2674,2902 2674,2902.48 D7.1@2591.97,2902.48
-5V_IN: C13.1 D3.1 L1.2 U4.1 | length 736.8
  Top Layer w35: L1.2@1666.97,2814.76 1764.69,2814.76 D3.1@1766.97,2812.48 ; U4.1@1776.97,2914.48 1776.97,2828.48 1766.97,2818.48 D3.1@1766.97,2812.48 ; C13.1@2246.97,2812.48 2186.97,2752.48 1826.97,2752.48 D3.1@1766.97,2812.48
AM4051_ENN: J2.7 Q6.2 U5.23 | length 1459.8
  Top Layer w6: Q6.2@1044.93,1266.33 1044.93,1355.43 1081.97,1392.48 1081.97,1540.16 1119.97,1578.16 1119.97,1900.48 1176.97,1957.48 J2.7@1176.97,1967.48 1228.33,2018.83 1301.33,2018.83 1386.33,2103.83 1792.33,2103.83 1798.23,2097.93 U5.23@1798.23,2074.17
AM4051_ENN1: Q6.3 R18.1 U3.6 | length 641.9
  Top Layer w6: R18.1@886.97,977.48 885.36,975.87 U3.6@773.11,975.87 731.59,975.87 720.97,986.48 720.97,1036.48 812.97,1128.48 977.97,1128.48 1029.47,1179.98 Q6.3@1082.33,1179.98
AM4051_S1: J2.4 Q3.2 U5.20 | length 1562.7
  Top Layer w6: Q3.2@1044.93,1416.33 1044.93,1531.11 1099.97,1586.16 1099.97,1905.48 1117.97,1923.48 1117.97,2083.48 1151.97,2117.48 1214.97,2117.48 1264.97,2167.48 J2.4@1276.97,2167.48 1280.62,2163.83 1832.33,2163.83 1892.72,2103.44 U5.20@1892.72,2074.17
AM4051_S2: J2.5 Q4.2 U5.21 | length 1775.9
  Top Layer w6: Q4.2@774.57,1264.98 774.57,1289.66 1079.97,1595.06 1079.97,1910.48 1096.97,1927.48 v1(1096.97,2067.48) ; J2.5@1176.97,2067.48 1191.97,2067.48 1243.33,2118.83 1318.33,2118.83 1343.33,2143.83 1817.33,2143.83 1861.23,2099.94 U5.21@1861.23,2074.17
  Bottom Layer w6: v1(1096.97,2067.48) J2.5@1176.97,2067.48
AM4051_S3: J2.6 Q5.2 U5.22 | length 1921.9
  Top Layer w6: Q5.2@534.57,1264.98 577.07,1307.48 767.3,1307.48 1059.97,1600.16 1059.97,1915.48 1076.97,1932.48 v1(1076.97,2017.48) ; J2.6@1276.97,2067.48 1301.97,2067.48 1358.33,2123.83 1807.33,2123.83 1829.73,2101.43 U5.22@1829.73,2074.17
  Bottom Layer w6: v1(1076.97,2017.48) 1226.97,2017.48 J2.6@1276.97,2067.48
AM4051_S11: Q3.3 R14.1 U3.11 | length 883.1
  Top Layer w6: R14.1@426.97,912.48 490.36,975.87 U3.11@540.83,975.87 635.36,975.87 802.97,1143.48 972.97,1143.48 1050.62,1221.13 1066.97,1221.13 1082.33,1236.48 ; 1082.33,1237.84 Q3.3@1082.33,1331.33
AM4051_S22: Q4.3 R13.1 U3.10 | length 475.9
  Top Layer w6: R13.1@426.97,977.48 450.95,1001.46 U3.10@540.83,1001.46 633.45,1001.46 Q4.3@811.97,1179.98 ; Q4.3@801.97,1189.98 Q4.3@806.97,1194.98
AM4051_S33: Q5.3 R17.1 U3.9 | length 299
  Top Layer w6: R17.1@426.97,1042.48 442.41,1027.05 U3.9@540.83,1027.05 566.97,1053.19 Q5.3@566.97,1194.98
AM4051_TX: J8.2 U3.3 | length 821.3
  Top Layer w6: v1(725.59,899.09) U3.3@773.11,899.09
  Bottom Layer w6: J8.2@446.97,1557.48 565.97,1438.48 565.97,1058.71 v1(725.59,899.09)
ANT1_TX: J15.2 U3.13 | length 776.3
  Top Layer w6: J15.2@502.76,312.8 686.97,497.01 686.97,688.98 637.43,738.52 637.43,817.02 v1(604.77,849.69) ; U3.13@540.83,924.69 v1(587.97,924.69)
  Bottom Layer w6: v1(587.97,924.69) 604.77,907.89 v1(604.77,849.69)
ANT2_TX: J16.2 U3.14 | length 762.4
  Top Layer w6: U3.14@540.83,899.09 617.36,899.09 670.97,845.48 670.97,749.58 722.83,697.72 722.83,491.62 857.76,356.69 J16.2@857.76,312.8
ANT3_TX: J17.2 U3.15 | length 1179
  Top Layer w6: U3.15@540.83,873.5 611.95,873.5 653.97,831.48 653.97,741.98 701.97,693.98 701.97,487.48 806.97,382.48 806.97,287.48 836.97,257.48 996.97,257.48 1052.29,312.8 J17.2@1212.76,312.8
ANT4_TX: J18.2 U3.12 | length 1480.2
  Top Layer w6: U3.12@540.83,950.28 607.18,950.28 687.97,869.48 687.97,757.58 736.97,708.58 736.97,497.48 861.97,372.48 1508.07,372.48 J18.2@1567.76,312.8
ANT5_TX: J19.2 U3.1 | length 439.3
  Top Layer w6: v1(773.11,729.34) U3.1@773.11,847.91
  Bottom Layer w6: J19.2@502.76,607.8 624.3,729.34 v1(773.11,729.34)
ANT6_TX: J20.2 U3.5 | length 455.5
  Top Layer w6: U3.5@773.11,950.28 737.77,950.28 703.97,916.48 703.97,761.58 J20.2@857.76,607.8
ANT7_TX: J21.2 U3.2 | length 549.7
  Top Layer w6: U3.2@773.11,873.5 947.05,873.5 J21.2@1212.76,607.8
ANT8_TX: J22.2 U3.4 | length 925.9
  Top Layer w6: U3.4@773.11,924.69 824.77,924.69 856.97,892.48 951.97,892.48 1171.97,672.48 1503.07,672.48 J22.2@1567.76,607.8
ANT_TX1: J2.12 J10.2 U5.28 | length 1521.4
  Top Layer w10: J2.12@1276.97,1767.48 1341.97,1767.48 1507.72,1933.23 U5.28@1720.28,1933.23
  Bottom Layer w10: J2.12@1276.97,1767.48 1341.97,1702.48 1341.97,1237.48 J10.2@1661.97,917.48
ANT_TX2: J2.16 J14.2 U5.32 | length 1205
  Top Layer w10: J2.16@1276.97,1567.48 1350.97,1567.48 1590.74,1807.24 U5.32@1720.28,1807.24
  Bottom Layer w10: J2.16@1276.97,1567.48 1306.97,1537.48 J14.2@1306.97,917.48
BEEP: J3.14 R11.1 U5.3 | length 2022.3
  Top Layer w6: U5.3@1829.73,1760.79 1829.73,1719.72 1931.97,1617.48 2526.97,1617.48 J3.14@2576.97,1667.48 2586.97,1667.48 3071.97,1182.48 R11.1@3071.97,707.48
CZ_RX: J2.9 J4.1 U5.25 | length 1678.5
  Top Layer w10: J2.9@1176.97,1867.48 1228.33,1918.83 1373.33,1918.83 1482.21,2027.72 U5.25@1720.28,2027.72
  Bottom Layer w10: J4.1@152.29,1884.06 213.86,1822.48 1086.97,1822.48 1131.97,1867.48 J2.9@1176.97,1867.48
CZ_TX1: J2.10 J4.3 J5.2 J8.1 J12.1 U5.26 | length 2931
  Top Layer w10: J12.1@152.29,1034.06 210.97,1092.74 210.97,1244.48 423.97,1457.48 J8.1@446.97,1457.48 ; J2.10@1276.97,1867.48 1381.97,1867.48 1510.71,1996.22 U5.26@1720.28,1996.22
  Bottom Layer w10: J4.3@152.29,2080.91 91.97,2020.59 91.97,1849.48 183.97,1757.48 381.97,1757.48 ; J8.1@446.97,1457.48 381.97,1522.48 381.97,1757.48 ; J2.10@1276.97,1867.48 1226.97,1817.48 1136.97,1817.48 1116.97,1797.48 381.97,1797.48 381.97,1757.48
CZ_TX2: J2.14 J6.2 J8.3 J12.3 U5.30 | length 2192.7
  Top Layer w10: J12.3@152.29,1230.91 219.97,1298.59 219.97,1538.42 J6.2@151.7,1606.69 202.48,1657.48 J8.3@446.97,1657.48 ; J2.14@1276.97,1667.48 1385.97,1667.48 1588.73,1870.24 U5.30@1720.28,1870.24
  Bottom Layer w10: J8.3@446.97,1657.48 556.97,1767.48 1076.97,1767.48 1126.97,1717.48 1226.97,1717.48 J2.14@1276.97,1667.48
